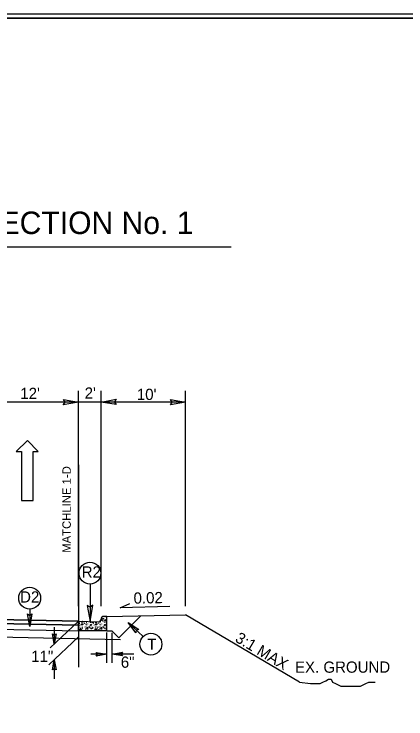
# Model space of a CAD drawing. Extents: x 2320980 to 2456309, y 595047 to 606177.
# Drawn here: x 2455930.6 to 2455976.9, y 597311.1 to 597394.6 of the extents above; entities that cross this region are included whole.
import ezdxf

# ---------------------------------------------------------------- set-up
doc = ezdxf.new("R2010")
doc.units = 0
for name, color, linetype in [('Matchline', 7, 'Continuous'), ('Matchline Text', 7, 'Continuous'), ('Old_Level_1', 7, 'Continuous'), ('Old_Level_2', 7, 'Continuous'), ('Old_Level_20', 7, 'Continuous'), ('Old_Level_21', 7, 'Continuous'), ('Old_Level_3', 7, 'Continuous'), ('Prop Dimension', 7, 'Continuous'), ('Prop Dimension Text', 7, 'Continuous'), ('Prop Lane Arrow CELL', 7, 'Continuous'), ('Prop Terminator CELL', 7, 'Continuous'), ('Sheet Plan CELL', 7, 'Continuous'), ('Sheet Plot Border Inside CELL', 7, 'Continuous'), ('Typical Berm CELL', 7, 'Continuous'), ('Typical Curb CELL', 7, 'Continuous'), ('Typical Hinge Slope Arterial CELL', 7, 'Continuous'), ('Typical ID Circle CELL', 7, 'Continuous'), ('Typical Pavement Slope CELL', 7, 'Continuous'), ('Typical Pavement Slope Information CELL', 7, 'Continuous'), ('Typical Terminator CELL', 7, 'Continuous')]:
    doc.layers.add(name, color=color, linetype=linetype)

msp = doc.modelspace()

# ---------------------------------------------------------------- linework, layer by layer
at = {"layer": 'Matchline'}
msp.add_line((2455938.194, 597341.198), (2455938.194, 597317.258), dxfattribs=at)
at = {"layer": 'Old_Level_21'}
for p, q in [((2455938.194, 597324.462), (2455938.194, 597349.968)), ((2455940.854, 597324.462), (2455940.854, 597349.968)), ((2455950.854, 597324.462), (2455950.854, 597349.968)), ((2455940.854, 597348.638), (2455912.754, 597348.638)), ((2455950.854, 597348.638), (2455940.854, 597348.638)), ((2455964.317, 597315.475), (2455950.854, 597323.449)), ((2455941.518, 597317.77), (2455941.518, 597321.361)), ((2455942.151, 597317.77), (2455942.151, 597321.314))]:
    msp.add_line(p, q, dxfattribs=at)
at = {"layer": 'Old_Level_3'}
for p, q in [((2455853.084, 597367.019), (2455956.259, 597367.019)), ((2455914.194, 597322.696), (2455938.194, 597322.222)), ((2455923.129, 597321.84), (2455938.194, 597321.542))]:
    msp.add_line(p, q, dxfattribs=at)
at = {"layer": 'Prop Dimension'}
for p, q in [((2455938.194, 597322.7), (2455934.816, 597319.518)), ((2455935.317, 597321.989), (2455935.317, 597319.989)), ((2455938.195, 597320.824), (2455934.69, 597317.521)), ((2455935.318, 597318.113), (2455935.318, 597315.862))]:
    msp.add_line(p, q, dxfattribs=at)
at = {"layer": 'Prop Dimension Text'}
for p, q in [((2455932.41, 597324.128), (2455932.41, 597322.045)), ((2455945.818, 597320.854), (2455944.059, 597322.535)), ((2455941.518, 597318.783), (2455939.631, 597318.783)), ((2455944.713, 597318.783), (2455942.151, 597318.783))]:
    msp.add_line(p, q, dxfattribs=at)
msp.add_lwpolyline([(2455948.976, 597324.441), (2455943.12, 597324.281), (2455944.257, 597324.769)], dxfattribs=at)
for centre in [(2455939.539, 597328.377), (2455932.41, 597325.42), (2455946.752, 597319.96)]:
    msp.add_circle(centre, 1.293, dxfattribs=at)
at = {"layer": 'Prop Lane Arrow CELL'}
for p, q in [((2455932.137, 597344.1), (2455930.807, 597342.791)), ((2455933.426, 597342.791), (2455932.137, 597344.1)), ((2455930.807, 597342.791), (2455931.431, 597342.791)), ((2455931.431, 597342.791), (2455931.431, 597336.972)), ((2455932.802, 597336.972), (2455932.802, 597342.791)), ((2455932.802, 597342.791), (2455933.426, 597342.791)), ((2455931.431, 597336.972), (2455932.802, 597336.972))]:
    msp.add_line(p, q, dxfattribs=at)
at = {"layer": 'Prop Terminator CELL'}
for points in [[(2455935.523, 597321.186), (2455935.317, 597319.989), (2455935.104, 597321.193), (2455935.317, 597321.04)], [(2455935.112, 597316.916), (2455935.318, 597318.113), (2455935.531, 597316.91), (2455935.318, 597317.062)]]:
    msp.add_lwpolyline(points, close=True, dxfattribs=at)
at = {"layer": 'Sheet Plan CELL'}
for points in [[(2455742.104, 597184.076), (2455742.099, 597394.071), (2456002.097, 597394.079), (2456002.099, 597364.066), (2456042.107, 597364.064), (2456042.107, 597184.076)], [(2456042.112, 597394.076), (2455742.104, 597394.076), (2455742.104, 597184.076), (2456042.107, 597184.076)]]:
    msp.add_lwpolyline(points, close=True, dxfattribs=at)
at = {"layer": 'Sheet Plot Border Inside CELL'}
msp.add_lwpolyline([(2455711.407, 597183.574), (2456044.604, 597183.576), (2456044.607, 597394.574), (2455711.407, 597394.574)], close=True, dxfattribs=at)
at = {"layer": 'Typical Berm CELL'}
for p, q in [((2455941.518, 597323.255), (2455950.854, 597323.449)), ((2455941.518, 597321.538), (2455942.141, 597321.538))]:
    msp.add_line(p, q, dxfattribs=at)
at = {"layer": 'Typical Curb CELL'}
for p, q in [((2455940.967, 597322.902), (2455941.05, 597323.055)), ((2455941.187, 597322.955), (2455940.967, 597322.902)), ((2455941.05, 597323.055), (2455941.187, 597322.955)), ((2455941.518, 597323.255), (2455941.172, 597323.255)), ((2455941.518, 597321.538), (2455941.518, 597323.255)), ((2455938.194, 597322.7), (2455940.521, 597322.604)), ((2455938.54, 597322.243), (2455938.655, 597322.403)), ((2455938.7, 597322.252), (2455938.54, 597322.243)), ((2455938.655, 597322.403), (2455938.7, 597322.252)), ((2455939.558, 597322.175), (2455939.641, 597322.328)), ((2455939.778, 597322.228), (2455939.558, 597322.175)), ((2455939.641, 597322.328), (2455939.778, 597322.228)), ((2455940.202, 597322.243), (2455940.316, 597322.403)), ((2455940.361, 597322.252), (2455940.202, 597322.243)), ((2455940.316, 597322.403), (2455940.361, 597322.252)), ((2455941.219, 597322.175), (2455941.302, 597322.328)), ((2455941.439, 597322.228), (2455941.219, 597322.175)), ((2455941.264, 597322.811), (2455941.287, 597322.691)), ((2455941.469, 597322.752), (2455941.264, 597322.811)), ((2455941.287, 597322.691), (2455941.469, 597322.752)), ((2455941.302, 597322.328), (2455941.439, 597322.228)), ((2455941.518, 597321.538), (2455938.194, 597321.538)), ((2455938.328, 597321.642), (2455938.443, 597321.802)), ((2455938.489, 597321.651), (2455938.328, 597321.642)), ((2455938.443, 597321.802), (2455938.489, 597321.651)), ((2455939.118, 597321.734), (2455939.232, 597321.893)), ((2455939.278, 597321.742), (2455939.118, 597321.734)), ((2455939.232, 597321.893), (2455939.278, 597321.742)), ((2455940.136, 597321.666), (2455940.219, 597321.819)), ((2455940.356, 597321.719), (2455940.136, 597321.666)), ((2455940.219, 597321.819), (2455940.356, 597321.719)), ((2455940.78, 597321.734), (2455940.893, 597321.893)), ((2455940.939, 597321.742), (2455940.78, 597321.734)), ((2455940.893, 597321.893), (2455940.939, 597321.742))]:
    msp.add_line(p, q, dxfattribs=at)
for centre in [(2455941.212, 597323.154), (2455941.5, 597323.108), (2455938.216, 597322.373), (2455938.238, 597322.502), (2455938.291, 597322.183), (2455938.313, 597322.457), (2455938.419, 597322.244), (2455938.457, 597322.622), (2455938.586, 597322.509), (2455938.647, 597322.645), (2455938.844, 597322.562), (2455938.882, 597322.426), (2455939.08, 597322.312), (2455939.118, 597322.54), (2455939.125, 597322.107), (2455939.14, 597322.607), (2455939.247, 597322.35), (2455939.482, 597322.569), (2455939.641, 597322.502), (2455939.877, 597322.373), (2455939.899, 597322.502), (2455939.953, 597322.183), (2455939.974, 597322.457), (2455940.08, 597322.244), (2455940.118, 597322.567), (2455940.247, 597322.509), (2455940.506, 597322.562), (2455940.543, 597322.426), (2455940.741, 597322.312), (2455940.779, 597322.54), (2455940.786, 597322.107), (2455940.802, 597322.607), (2455940.908, 597322.35), (2455940.926, 597322.781), (2455941.085, 597322.714), (2455941.143, 597322.569), (2455941.303, 597322.502), (2455941.432, 597322.865), (2455938.208, 597321.963), (2455938.412, 597321.864), (2455938.487, 597321.933), (2455938.647, 597321.947), (2455938.671, 597321.825), (2455938.7, 597322.024), (2455938.973, 597321.993), (2455938.997, 597321.735), (2455939.201, 597321.955), (2455939.436, 597322.039), (2455939.46, 597321.917), (2455939.657, 597321.803), (2455939.664, 597321.986), (2455939.703, 597321.598), (2455939.824, 597321.841), (2455939.869, 597321.963), (2455940.149, 597321.933), (2455940.219, 597321.993), (2455940.361, 597322.024), (2455940.454, 597321.864), (2455940.477, 597321.993), (2455940.53, 597321.674), (2455940.552, 597321.947), (2455940.634, 597321.993), (2455940.658, 597321.735), (2455940.862, 597321.955), (2455941.098, 597322.039), (2455941.121, 597321.917), (2455941.319, 597321.803), (2455941.325, 597321.986), (2455941.364, 597321.598), (2455941.486, 597321.841)]:
    msp.add_circle(centre, 0.0107, dxfattribs=at)
for centre, start, end in [((2455941.172, 597322.936), 90, 180), ((2455940.534, 597322.922), 267.61554, 0)]:
    msp.add_arc(centre, 0.319, start, end, dxfattribs=at)
at = {"layer": 'Typical Hinge Slope Arterial CELL'}
msp.add_lwpolyline([(2455964.317, 597315.475), (2455965.627, 597315.312), (2455965.955, 597315.312), (2455966.447, 597315.312), (2455966.775, 597315.312), (2455967.103, 597315.476), (2455967.43, 597315.64), (2455967.758, 597315.805), (2455968.086, 597315.805), (2455968.25, 597315.476), (2455968.578, 597315.313), (2455968.906, 597315.148), (2455969.233, 597314.985), (2455969.561, 597314.985), (2455969.889, 597314.985), (2455970.216, 597314.985), (2455970.544, 597314.986), (2455970.872, 597314.986), (2455971.199, 597314.986), (2455971.527, 597314.986), (2455971.855, 597315.149), (2455972.182, 597315.314), (2455972.51, 597315.477), (2455973.002, 597315.477), (2455973.273, 597315.477)], dxfattribs=at)
at = {"layer": 'Typical ID Circle CELL'}
msp.add_line((2455939.551, 597327.085), (2455939.551, 597322.668), dxfattribs=at)
at = {"layer": 'Typical Pavement Slope CELL'}
for p, q in [((2455914.194, 597323.18), (2455938.194, 597322.7)), ((2455938.194, 597322.7), (2455914.194, 597323.18)), ((2455945.559, 597323.339), (2455942.95, 597320.729)), ((2455914.194, 597322.696), (2455938.194, 597322.222)), ((2455938.194, 597322.222), (2455927.142, 597322.44)), ((2455938.194, 597322.222), (2455938.194, 597322.7)), ((2455938.194, 597321.542), (2455938.194, 597322.222)), ((2455923.129, 597321.84), (2455938.194, 597321.542)), ((2455942.141, 597321.538), (2455942.95, 597320.729)), ((2455923.129, 597320.936), (2455943.143, 597320.536))]:
    msp.add_line(p, q, dxfattribs=at)
at = {"layer": 'Typical Terminator CELL'}
for points in [[(2455936.398, 597348.947), (2455938.194, 597348.638), (2455936.388, 597348.318), (2455936.617, 597348.638)], [(2455942.649, 597348.328), (2455940.854, 597348.638), (2455942.659, 597348.957), (2455942.43, 597348.638)], [(2455949.058, 597348.947), (2455950.854, 597348.638), (2455949.048, 597348.318), (2455949.277, 597348.638)], [(2455939.224, 597324.563), (2455939.551, 597322.668), (2455939.887, 597324.573), (2455939.551, 597324.331)], [(2455932.668, 597323.541), (2455932.41, 597322.045), (2455932.144, 597323.549), (2455932.41, 597323.358)], [(2455944.962, 597321.314), (2455944.059, 597322.535), (2455945.33, 597321.687), (2455945.008, 597321.627)], [(2455940.271, 597318.997), (2455941.518, 597318.783), (2455940.264, 597318.561), (2455940.424, 597318.783)], [(2455943.398, 597318.568), (2455942.151, 597318.783), (2455943.405, 597319.004), (2455943.245, 597318.783)]]:
    msp.add_lwpolyline(points, close=True, dxfattribs=at)

# ---------------------------------------------------------------- texts
at = {"layer": 'Matchline Text'}
msp.add_text('MATCHLINE 1-D', height=1, rotation=90, dxfattribs=at).set_placement((2455937.275, 597330.79))
at = {"layer": 'Old_Level_1'}
msp.add_text('EX. GROUND', height=1.33, rotation=0.08974, dxfattribs=at).set_placement((2455963.794, 597316.573))
at = {"layer": 'Old_Level_2'}
msp.add_text('TRANSITION FROM EXISTING TO TYPICAL SECTION No. 1', height=2.66, dxfattribs=at).set_placement((2455853.158, 597368.529))
at = {"layer": 'Old_Level_20'}
for s, p in [('R2', (2455938.561, 597327.848)), ('T', (2455946.315, 597319.295))]:
    msp.add_text(s, height=1.33, dxfattribs=at).set_placement(p)
msp.add_text('D2', height=1.33, rotation=359.99718, dxfattribs=at).set_placement((2455931.276, 597324.891))
at = {"layer": 'Old_Level_21'}
for s, p in [("12'", (2455931.303, 597348.996)), ("10'", (2455945.084, 597348.879)), ('6"', (2455943.19, 597317.172))]:
    msp.add_text(s, height=1.33, dxfattribs=at).set_placement(p)
for s, rotation, p in [("2'", 0.00016, (2455938.914, 597349.034)), ('0.02', 1.14561, (2455944.711, 597324.757)), ('3:1 MAX', 329.36161, (2455956.604, 597320.335))]:
    msp.add_text(s, height=1.33, rotation=rotation, dxfattribs=at).set_placement(p)
at = {"layer": 'Typical Pavement Slope Information CELL'}
msp.add_text('11"', height=1.33, dxfattribs=at).set_placement((2455932.589, 597317.859))

doc.saveas('drawing.dxf')
